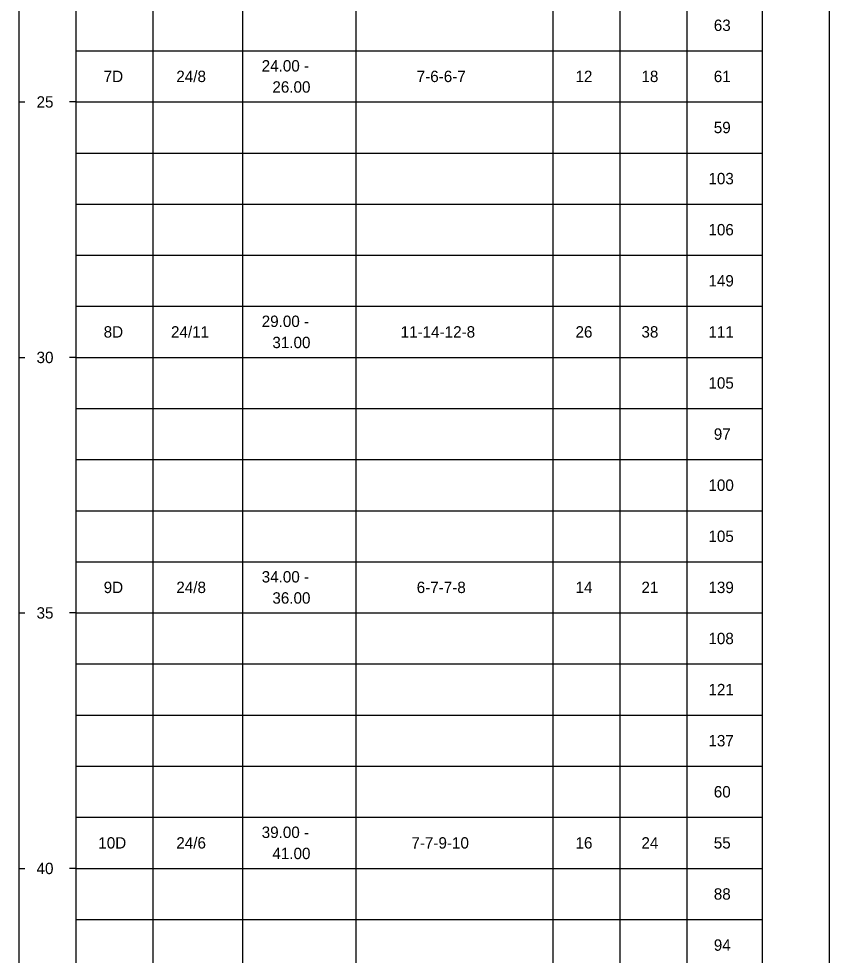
# Model space of a CAD drawing. Extents: x 9422 to 9552, y 6780 to 6860.
# Drawn here: x 9422.45 to 9438.31, y 6805.31 to 6823.64 of the extents above; entities that cross this region are included whole.
import ezdxf

# ---------------------------------------------------------------- set-up
doc = ezdxf.new("R2010")
doc.units = 0
doc.layers.add('7', color=7, linetype='Continuous')

msp = doc.modelspace()

# ---------------------------------------------------------------- linework, layer by layer
at = {"layer": '7'}
for p, q in [((9438.314, 6834.011), (9438.314, 6822.011)), ((9438.314, 6822.011), (9438.314, 6798.011))]:
    msp.add_line(p, q, dxfattribs=at)
for points in [[(9422.449, 6860.114), (9422.449, 6821.983)], [(9423.567, 6850.528), (9423.567, 6821.983)], [(9438.314, 6850.528), (9438.314, 6821.983)], [(9425.076, 6849.992), (9425.076, 6821.983)], [(9426.831, 6849.992), (9426.831, 6821.983)], [(9429.046, 6849.992), (9429.046, 6821.983)], [(9432.901, 6849.992), (9432.901, 6821.983)], [(9434.213, 6849.992), (9434.213, 6821.983)], [(9435.526, 6849.992), (9435.526, 6821.983)], [(9437.002, 6849.992), (9437.002, 6821.983)], [(9423.567, 6823.011), (9425.076, 6823.011)], [(9425.076, 6823.011), (9426.831, 6823.011)], [(9426.831, 6823.011), (9429.046, 6823.011)], [(9429.046, 6823.011), (9432.901, 6823.011)], [(9432.901, 6823.011), (9434.213, 6823.011)], [(9434.213, 6823.011), (9435.526, 6823.011)], [(9435.526, 6823.011), (9437.002, 6823.011)], [(9422.449, 6822.038), (9422.449, 6796.983)], [(9422.449, 6822.011), (9422.571, 6822.011)], [(9423.567, 6822.011), (9423.445, 6822.011)], [(9423.567, 6822.038), (9423.567, 6796.983)], [(9423.567, 6822.011), (9425.076, 6822.011)], [(9425.076, 6822.038), (9425.076, 6796.983)], [(9425.076, 6822.011), (9426.831, 6822.011)], [(9426.831, 6822.038), (9426.831, 6796.983)], [(9426.831, 6822.011), (9429.046, 6822.011)], [(9429.046, 6822.038), (9429.046, 6796.983)], [(9429.046, 6822.011), (9432.901, 6822.011)], [(9432.901, 6822.038), (9432.901, 6796.983)], [(9432.901, 6822.011), (9434.213, 6822.011)], [(9434.213, 6822.038), (9434.213, 6796.983)], [(9434.213, 6822.011), (9435.526, 6822.011)], [(9435.526, 6822.038), (9435.526, 6796.983)], [(9435.526, 6822.011), (9437.002, 6822.011)], [(9437.002, 6822.038), (9437.002, 6796.983)], [(9438.314, 6822.038), (9438.314, 6796.983)], [(9423.567, 6821.011), (9425.076, 6821.011)], [(9425.076, 6821.011), (9426.831, 6821.011)], [(9426.831, 6821.011), (9429.046, 6821.011)], [(9429.046, 6821.011), (9432.901, 6821.011)], [(9432.901, 6821.011), (9434.213, 6821.011)], [(9434.213, 6821.011), (9435.526, 6821.011)], [(9435.526, 6821.011), (9437.002, 6821.011)], [(9423.567, 6820.011), (9425.076, 6820.011)], [(9425.076, 6820.011), (9426.831, 6820.011)], [(9426.831, 6820.011), (9429.046, 6820.011)], [(9429.046, 6820.011), (9432.901, 6820.011)], [(9432.901, 6820.011), (9434.213, 6820.011)], [(9434.213, 6820.011), (9435.526, 6820.011)], [(9435.526, 6820.011), (9437.002, 6820.011)], [(9423.567, 6819.011), (9425.076, 6819.011)], [(9425.076, 6819.011), (9426.831, 6819.011)], [(9426.831, 6819.011), (9429.046, 6819.011)], [(9429.046, 6819.011), (9432.901, 6819.011)], [(9432.901, 6819.011), (9434.213, 6819.011)], [(9434.213, 6819.011), (9435.526, 6819.011)], [(9435.526, 6819.011), (9437.002, 6819.011)], [(9423.567, 6818.011), (9425.076, 6818.011)], [(9425.076, 6818.011), (9426.831, 6818.011)], [(9426.831, 6818.011), (9429.046, 6818.011)], [(9429.046, 6818.011), (9432.901, 6818.011)], [(9432.901, 6818.011), (9434.213, 6818.011)], [(9434.213, 6818.011), (9435.526, 6818.011)], [(9435.526, 6818.011), (9437.002, 6818.011)], [(9422.449, 6817.011), (9422.571, 6817.011)], [(9423.567, 6817.011), (9423.445, 6817.011)], [(9423.567, 6817.011), (9425.076, 6817.011)], [(9425.076, 6817.011), (9426.831, 6817.011)], [(9426.831, 6817.011), (9429.046, 6817.011)], [(9429.046, 6817.011), (9432.901, 6817.011)], [(9432.901, 6817.011), (9434.213, 6817.011)], [(9434.213, 6817.011), (9435.526, 6817.011)], [(9435.526, 6817.011), (9437.002, 6817.011)], [(9423.567, 6816.011), (9425.076, 6816.011)], [(9425.076, 6816.011), (9426.831, 6816.011)], [(9426.831, 6816.011), (9429.046, 6816.011)], [(9429.046, 6816.011), (9432.901, 6816.011)], [(9432.901, 6816.011), (9434.213, 6816.011)], [(9434.213, 6816.011), (9435.526, 6816.011)], [(9435.526, 6816.011), (9437.002, 6816.011)], [(9423.567, 6815.011), (9425.076, 6815.011)], [(9425.076, 6815.011), (9426.831, 6815.011)], [(9426.831, 6815.011), (9429.046, 6815.011)], [(9429.046, 6815.011), (9432.901, 6815.011)], [(9432.901, 6815.011), (9434.213, 6815.011)], [(9434.213, 6815.011), (9435.526, 6815.011)], [(9435.526, 6815.011), (9437.002, 6815.011)], [(9423.567, 6814.011), (9425.076, 6814.011)], [(9425.076, 6814.011), (9426.831, 6814.011)], [(9426.831, 6814.011), (9429.046, 6814.011)], [(9429.046, 6814.011), (9432.901, 6814.011)], [(9432.901, 6814.011), (9434.213, 6814.011)], [(9434.213, 6814.011), (9435.526, 6814.011)], [(9435.526, 6814.011), (9437.002, 6814.011)], [(9423.567, 6813.011), (9425.076, 6813.011)], [(9425.076, 6813.011), (9426.831, 6813.011)], [(9426.831, 6813.011), (9429.046, 6813.011)], [(9429.046, 6813.011), (9432.901, 6813.011)], [(9432.901, 6813.011), (9434.213, 6813.011)], [(9434.213, 6813.011), (9435.526, 6813.011)], [(9435.526, 6813.011), (9437.002, 6813.011)], [(9422.449, 6812.011), (9422.571, 6812.011)], [(9423.567, 6812.011), (9423.445, 6812.011)], [(9423.567, 6812.011), (9425.076, 6812.011)], [(9425.076, 6812.011), (9426.831, 6812.011)], [(9426.831, 6812.011), (9429.046, 6812.011)], [(9429.046, 6812.011), (9432.901, 6812.011)], [(9432.901, 6812.011), (9434.213, 6812.011)], [(9434.213, 6812.011), (9435.526, 6812.011)], [(9435.526, 6812.011), (9437.002, 6812.011)], [(9423.567, 6811.011), (9425.076, 6811.011)], [(9425.076, 6811.011), (9426.831, 6811.011)], [(9426.831, 6811.011), (9429.046, 6811.011)], [(9429.046, 6811.011), (9432.901, 6811.011)], [(9432.901, 6811.011), (9434.213, 6811.011)], [(9434.213, 6811.011), (9435.526, 6811.011)], [(9435.526, 6811.011), (9437.002, 6811.011)], [(9423.567, 6810.011), (9425.076, 6810.011)], [(9425.076, 6810.011), (9426.831, 6810.011)], [(9426.831, 6810.011), (9429.046, 6810.011)], [(9429.046, 6810.011), (9432.901, 6810.011)], [(9432.901, 6810.011), (9434.213, 6810.011)], [(9434.213, 6810.011), (9435.526, 6810.011)], [(9435.526, 6810.011), (9437.002, 6810.011)], [(9423.567, 6809.011), (9425.076, 6809.011)], [(9425.076, 6809.011), (9426.831, 6809.011)], [(9426.831, 6809.011), (9429.046, 6809.011)], [(9429.046, 6809.011), (9432.901, 6809.011)], [(9432.901, 6809.011), (9434.213, 6809.011)], [(9434.213, 6809.011), (9435.526, 6809.011)], [(9435.526, 6809.011), (9437.002, 6809.011)], [(9423.567, 6808.011), (9425.076, 6808.011)], [(9425.076, 6808.011), (9426.831, 6808.011)], [(9426.831, 6808.011), (9429.046, 6808.011)], [(9429.046, 6808.011), (9432.901, 6808.011)], [(9432.901, 6808.011), (9434.213, 6808.011)], [(9434.213, 6808.011), (9435.526, 6808.011)], [(9435.526, 6808.011), (9437.002, 6808.011)], [(9422.449, 6807.011), (9422.571, 6807.011)], [(9423.567, 6807.011), (9423.445, 6807.011)], [(9423.567, 6807.011), (9425.076, 6807.011)], [(9425.076, 6807.011), (9426.831, 6807.011)], [(9426.831, 6807.011), (9429.046, 6807.011)], [(9429.046, 6807.011), (9432.901, 6807.011)], [(9432.901, 6807.011), (9434.213, 6807.011)], [(9434.213, 6807.011), (9435.526, 6807.011)], [(9435.526, 6807.011), (9437.002, 6807.011)], [(9423.567, 6806.011), (9425.076, 6806.011)], [(9425.076, 6806.011), (9426.831, 6806.011)], [(9426.831, 6806.011), (9429.046, 6806.011)], [(9429.046, 6806.011), (9432.901, 6806.011)], [(9432.901, 6806.011), (9434.213, 6806.011)], [(9434.213, 6806.011), (9435.526, 6806.011)], [(9435.526, 6806.011), (9437.002, 6806.011)]]:
    msp.add_lwpolyline(points, dxfattribs=at)

# ---------------------------------------------------------------- texts
for s, p in [('63', (9436.054, 6823.399)), ('24.00 -', (9427.205, 6822.606)), ('7D', (9424.112, 6822.399)), ('24/8', (9425.534, 6822.399)), ('7-6-6-7', (9430.239, 6822.399)), ('12', (9433.347, 6822.399)), (' 18', (9434.555, 6822.399)), ('61', (9436.054, 6822.399)), ('26.00', (9427.414, 6822.192)), ('25', (9422.798, 6821.899)), ('59', (9436.054, 6821.399)), ('103', (9435.949, 6820.399)), ('106', (9435.949, 6819.399)), ('149', (9435.949, 6818.399)), ('29.00 -', (9427.205, 6817.606)), ('8D', (9424.112, 6817.399)), ('24/11', (9425.43, 6817.399)), ('11-14-12-8', (9429.925, 6817.399)), ('26', (9433.347, 6817.399)), (' 38', (9434.555, 6817.399)), ('111', (9435.949, 6817.399)), ('31.00', (9427.414, 6817.192)), ('30', (9422.798, 6816.899)), ('105', (9435.949, 6816.399)), ('97', (9436.054, 6815.399)), ('100', (9435.949, 6814.399)), ('105', (9435.949, 6813.399)), ('34.00 -', (9427.205, 6812.606)), ('9D', (9424.112, 6812.399)), ('24/8', (9425.534, 6812.399)), ('6-7-7-8', (9430.239, 6812.399)), ('14', (9433.347, 6812.399)), (' 21', (9434.555, 6812.399)), ('139', (9435.949, 6812.399)), ('36.00', (9427.414, 6812.192)), ('35', (9422.798, 6811.899)), ('108', (9435.949, 6811.399)), ('121', (9435.949, 6810.399)), ('137', (9435.949, 6809.399)), ('60', (9436.054, 6808.399)), ('39.00 -', (9427.205, 6807.606)), ('24/6', (9425.534, 6807.399)), ('10D', (9424.007, 6807.399)), ('7-7-9-10', (9430.135, 6807.399)), ('16', (9433.347, 6807.399)), (' 24', (9434.555, 6807.399)), ('55', (9436.054, 6807.399)), ('41.00', (9427.414, 6807.192)), ('40', (9422.798, 6806.899)), ('88', (9436.054, 6806.399)), ('94', (9436.054, 6805.399))]:
    msp.add_text(s, height=0.2228, dxfattribs=at).set_placement(p)

doc.saveas('drawing.dxf')
